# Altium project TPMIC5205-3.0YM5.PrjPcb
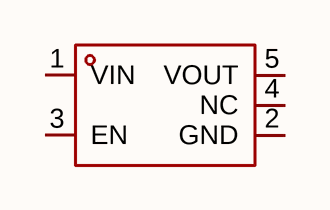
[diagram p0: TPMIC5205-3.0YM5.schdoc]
1 sheet, 1 parts. Net scope: global (net labels, ports and power ports of the same name join across sheets).

## Sheet TPMIC5205-3.0YM5.schdoc
size 127 x 101 mm

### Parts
U?  tpmic5205-3.0ym5  [SOT-23-5_L3.0-W1.7-P0.95-LS2.8-BL]  (value not drawn)

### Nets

Not connected (* = marked no-connect by the designer): U? 1(VIN) 2(GND) 3(EN) 4(NC) 5(VOUT)

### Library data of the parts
U? = tpmic5205-3.0ym5: 输出极性:正极;工作电压:20V;输出电压:3V;输出电流:150mA;电源纹波抑制比(PSRR):70dB@(1kHz);输出类型:固定;; Manufacturer: TECH PUBLIC(台舟); AddInBom: yes; ModelId: 0a2a1b8f50944f73965918ad6e5fe167; ModelName: SOT-23-5_L2.9-W1.6-H1.1-LS2.8-P0.95; ModelTransform: 118.60433,114.173,0,90,0,0,0.0005,0.0005,0; Output Configuration: 正极; Voltage - Supply: 20V; Output Voltage: 3V; Output Current: 150mA; Voltage Dropout: 180mV@(50mA); standby current: 2uA; Output Type: 固定; Number of Outputs: 1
